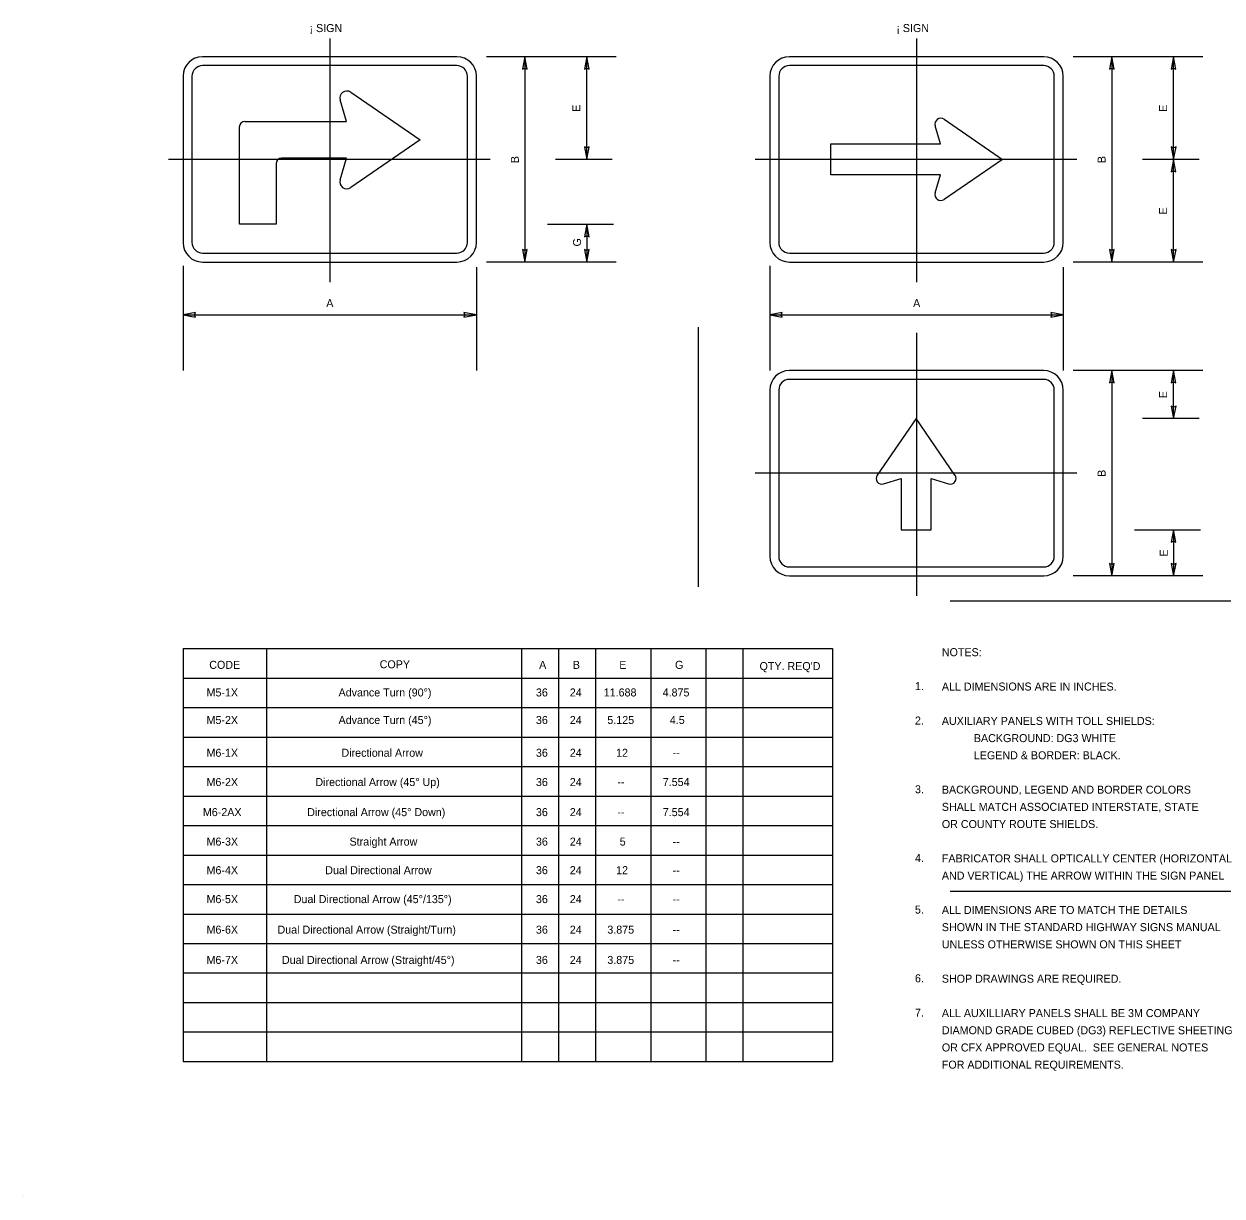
# Model space of a CAD drawing. Extents: x 60714 to 61343, y 8039 to 8449.
# Drawn here: x 60713.6 to 61132.8, y 8039 to 8449.1 of the extents above; entities that cross this region are included whole.
import ezdxf

# ---------------------------------------------------------------- set-up
doc = ezdxf.new("R2010")
doc.units = 0
for name, color, linetype in [('AdhocPoint_dp', 7, 'Continuous'), ('DimLines_dp', 7, 'Continuous'), ('SignPanel', 7, 'Continuous'), ('TextNotes', 7, 'Continuous'), ('TextTables', 7, 'Continuous')]:
    doc.layers.add(name, color=color, linetype=linetype)

msp = doc.modelspace()

# ---------------------------------------------------------------- linework, layer by layer
at = {"layer": 'AdhocPoint_dp'}
msp.add_line((60713.58, 8038.97), (60713.58, 8038.97), dxfattribs=at)
at = {"layer": 'DimLines_dp'}
for p, q in [((60820.57, 8444.01), (60820.57, 8358.79)), ((61025.91, 8444.01), (61025.91, 8358.79)), ((60920.81, 8437.66), (60875.43, 8437.66)), ((60888.88, 8437.66), (60888.04, 8433.31)), ((60888.88, 8437.66), (60888.88, 8365.8)), ((60889.69, 8433.31), (60888.88, 8437.66)), ((60910.54, 8437.66), (60909.7, 8433.31)), ((60910.54, 8401.73), (60910.54, 8437.66)), ((60911.35, 8433.31), (60910.54, 8437.66)), ((61126.14, 8437.66), (61080.77, 8437.66)), ((61094.22, 8437.66), (61093.38, 8433.31)), ((61094.22, 8437.66), (61094.22, 8365.8)), ((61095.03, 8433.31), (61094.22, 8437.66)), ((61115.88, 8437.66), (61115.04, 8433.31)), ((61115.88, 8401.73), (61115.88, 8437.66)), ((61116.69, 8433.31), (61115.88, 8437.66)), ((60888.04, 8433.31), (60888.88, 8433.64)), ((60888.88, 8433.64), (60889.69, 8433.31)), ((60909.7, 8433.31), (60910.54, 8433.64)), ((60910.54, 8433.64), (60911.35, 8433.31)), ((61093.38, 8433.31), (61094.22, 8433.64)), ((61094.22, 8433.64), (61095.03, 8433.31)), ((61115.04, 8433.31), (61115.88, 8433.64)), ((61115.88, 8433.64), (61116.69, 8433.31)), ((60910.54, 8405.75), (60909.73, 8406.08)), ((60909.73, 8406.08), (60910.54, 8401.73)), ((60910.54, 8401.73), (60911.38, 8406.08)), ((60911.38, 8406.08), (60910.54, 8405.75)), ((61115.88, 8405.75), (61115.07, 8406.08)), ((61115.07, 8406.08), (61115.88, 8401.73)), ((61115.88, 8401.73), (61116.72, 8406.08)), ((61116.72, 8406.08), (61115.88, 8405.75)), ((60876.68, 8401.73), (60764.15, 8401.73)), ((60919.44, 8401.73), (60899.62, 8401.73)), ((61082.02, 8401.73), (60969.48, 8401.73)), ((61124.77, 8401.73), (61104.95, 8401.73)), ((61115.88, 8401.73), (61115.04, 8397.38)), ((61115.88, 8365.8), (61115.88, 8401.73)), ((61116.69, 8397.38), (61115.88, 8401.73)), ((61115.04, 8397.38), (61115.88, 8397.71)), ((61115.88, 8397.71), (61116.69, 8397.38)), ((60896.81, 8379.02), (60919.89, 8379.02)), ((60910.54, 8379.02), (60909.7, 8374.67)), ((60910.54, 8379.02), (60910.54, 8365.8)), ((60911.35, 8374.67), (60910.54, 8379.02)), ((60909.7, 8374.67), (60910.54, 8375)), ((60910.54, 8375), (60911.35, 8374.67)), ((60888.88, 8369.82), (60888.07, 8370.15)), ((60888.07, 8370.15), (60888.88, 8365.8)), ((60888.88, 8365.8), (60889.72, 8370.15)), ((60889.72, 8370.15), (60888.88, 8369.82)), ((60910.54, 8369.82), (60909.73, 8370.15)), ((60909.73, 8370.15), (60910.54, 8365.8)), ((60910.54, 8365.8), (60911.38, 8370.15)), ((60911.38, 8370.15), (60910.54, 8369.82)), ((61094.22, 8369.82), (61093.41, 8370.15)), ((61093.41, 8370.15), (61094.22, 8365.8)), ((61094.22, 8365.8), (61095.06, 8370.15)), ((61095.06, 8370.15), (61094.22, 8369.82)), ((61115.88, 8369.82), (61115.07, 8370.15)), ((61115.07, 8370.15), (61115.88, 8365.8)), ((61115.88, 8365.8), (61116.72, 8370.15)), ((61116.72, 8370.15), (61115.88, 8369.82)), ((60769.24, 8364.46), (60769.24, 8327.85)), ((60871.91, 8364.01), (60871.91, 8327.85)), ((60920.81, 8365.8), (60875.43, 8365.8)), ((60974.58, 8364.46), (60974.58, 8327.85)), ((61077.24, 8364.01), (61077.24, 8327.85)), ((61126.14, 8365.8), (61080.77, 8365.8)), ((60773.59, 8348.12), (60769.24, 8347.31)), ((60769.24, 8347.31), (60871.91, 8347.31)), ((60769.24, 8347.31), (60773.59, 8346.47)), ((60773.26, 8347.31), (60773.59, 8348.12)), ((60773.59, 8346.47), (60773.26, 8347.31)), ((60871.91, 8347.31), (60867.56, 8348.15)), ((60867.56, 8348.15), (60867.89, 8347.31)), ((60867.89, 8347.31), (60867.56, 8346.5)), ((60867.56, 8346.5), (60871.91, 8347.31)), ((60978.93, 8348.12), (60974.58, 8347.31)), ((60974.58, 8347.31), (61077.24, 8347.31)), ((60974.58, 8347.31), (60978.93, 8346.47)), ((60978.6, 8347.31), (60978.93, 8348.12)), ((60978.93, 8346.47), (60978.6, 8347.31)), ((61077.24, 8347.31), (61072.89, 8348.15)), ((61072.89, 8348.15), (61073.22, 8347.31)), ((61073.22, 8347.31), (61072.89, 8346.5)), ((61072.89, 8346.5), (61077.24, 8347.31)), ((60949.64, 8252.13), (60949.64, 8343.04)), ((61025.91, 8341.08), (61025.91, 8248.98)), ((61126.14, 8327.85), (61080.77, 8327.85)), ((61094.22, 8327.85), (61093.38, 8323.5)), ((61094.22, 8327.85), (61094.22, 8255.99)), ((61095.03, 8323.5), (61094.22, 8327.85)), ((61115.88, 8327.85), (61115.04, 8323.5)), ((61115.88, 8311.05), (61115.88, 8327.85)), ((61116.69, 8323.5), (61115.88, 8327.85)), ((61093.38, 8323.5), (61094.22, 8323.83)), ((61094.22, 8323.83), (61095.03, 8323.5)), ((61115.04, 8323.5), (61115.88, 8323.83)), ((61115.88, 8323.83), (61116.69, 8323.5)), ((61115.88, 8315.07), (61115.07, 8315.4)), ((61115.07, 8315.4), (61115.88, 8311.05)), ((61115.88, 8311.05), (61116.72, 8315.4)), ((61116.72, 8315.4), (61115.88, 8315.07)), ((61124.77, 8311.05), (61104.95, 8311.05)), ((61082.02, 8291.92), (60969.48, 8291.92)), ((61102.15, 8272.13), (61125.22, 8272.13)), ((61115.88, 8272.13), (61115.04, 8267.78)), ((61115.88, 8272.13), (61115.88, 8255.99)), ((61116.69, 8267.78), (61115.88, 8272.13)), ((61115.04, 8267.78), (61115.88, 8268.11)), ((61115.88, 8268.11), (61116.69, 8267.78)), ((61094.22, 8260.01), (61093.41, 8260.34)), ((61093.41, 8260.34), (61094.22, 8255.99)), ((61094.22, 8255.99), (61095.06, 8260.34)), ((61095.06, 8260.34), (61094.22, 8260.01)), ((61115.88, 8260.01), (61115.07, 8260.34)), ((61115.07, 8260.34), (61115.88, 8255.99)), ((61115.88, 8255.99), (61116.72, 8260.34)), ((61116.72, 8260.34), (61115.88, 8260.01)), ((61126.14, 8255.99), (61080.77, 8255.99))]:
    msp.add_line(p, q, dxfattribs=at)
at = {"layer": 'SignPanel'}
for p, q in [((60826.45, 8414.96), (60824.19, 8422.51)), ((60827.92, 8425.23), (60852.2, 8408.54)), ((60790.9, 8414.96), (60826.45, 8414.96)), ((61035.54, 8415.74), (61055.94, 8401.73)), ((60788.95, 8379.02), (60788.95, 8413.01)), ((61034.31, 8407.12), (61032.41, 8413.46)), ((60852.2, 8408.54), (60827.92, 8391.86)), ((60995.88, 8407.12), (61034.31, 8407.12)), ((60995.88, 8396.34), (60995.88, 8407.12)), ((60826.45, 8402.13), (60803.74, 8402.13)), ((60824.19, 8394.58), (60826.45, 8402.13)), ((61055.94, 8401.73), (61035.54, 8387.72)), ((60801.78, 8400.17), (60801.78, 8379.02)), ((61034.31, 8396.34), (60995.88, 8396.34)), ((61032.41, 8390), (61034.31, 8396.34)), ((60801.78, 8379.02), (60788.95, 8379.02)), ((61025.75, 8311.05), (61012.13, 8291.22)), ((61039.37, 8291.22), (61025.75, 8311.05)), ((61014.34, 8288.18), (61020.51, 8290.02)), ((61020.51, 8290.02), (61020.51, 8272.13)), ((61030.99, 8272.13), (61030.99, 8290.02)), ((61030.99, 8290.02), (61037.15, 8288.18)), ((61020.51, 8272.13), (61030.99, 8272.13))]:
    msp.add_line(p, q, dxfattribs=at)
for points in [[(60865.06, 8437.66), (60776.09, 8437.66)], [(61070.4, 8437.66), (60981.42, 8437.66)], [(60769.24, 8430.82), (60769.24, 8372.64)], [(60772.38, 8430.82), (60772.38, 8372.64)], [(60865.06, 8434.53), (60776.09, 8434.53)], [(60868.77, 8372.64), (60868.77, 8430.82)], [(60871.91, 8372.64), (60871.91, 8430.82)], [(60974.58, 8430.82), (60974.58, 8372.64)], [(60977.71, 8430.82), (60977.71, 8372.64)], [(61070.4, 8434.53), (60981.42, 8434.53)], [(61074.11, 8372.64), (61074.11, 8430.82)], [(61077.24, 8372.64), (61077.24, 8430.82)], [(60776.09, 8368.93), (60865.06, 8368.93)], [(60981.42, 8368.93), (61070.4, 8368.93)], [(60776.09, 8365.8), (60865.06, 8365.8)], [(60981.42, 8365.8), (61070.4, 8365.8)], [(61070.4, 8327.85), (60981.42, 8327.85)], [(61070.4, 8324.72), (60981.42, 8324.72)], [(60974.58, 8321.01), (60974.58, 8262.83)], [(60977.71, 8321.01), (60977.71, 8262.83)], [(61074.11, 8262.83), (61074.11, 8321.01)], [(61077.24, 8262.83), (61077.24, 8321.01)], [(60981.42, 8259.12), (61070.4, 8259.12)], [(60981.42, 8255.99), (61070.4, 8255.99)]]:
    msp.add_lwpolyline(points, dxfattribs=at)
for centre, radius, start, end in [((60776.09, 8430.82), 6.84, 90, 180), ((60865.06, 8430.82), 6.84, 360, 90), ((60981.42, 8430.82), 6.84, 90, 180), ((61070.4, 8430.82), 6.84, 360, 90), ((60776.09, 8430.82), 3.71, 90, 179.9456), ((60865.06, 8430.82), 3.71, 0.0544, 90), ((60981.42, 8430.82), 3.71, 90, 179.9456), ((61070.4, 8430.82), 3.71, 0.0544, 90), ((60826.53, 8423.21), 2.44, 55.5119, 196.6443), ((60790.9, 8413.01), 1.96, 90, 180), ((61034.38, 8414.05), 2.05, 55.5119, 196.6443), ((60803.74, 8400.17), 1.96, 90, 180), ((60826.53, 8393.88), 2.44, 163.3557, 304.4881), ((61034.38, 8389.41), 2.05, 163.3557, 304.4881), ((60776.09, 8372.64), 6.84, 180, 270), ((60776.09, 8372.64), 3.71, 180, 270), ((60865.06, 8372.64), 6.84, 270, 0), ((60865.06, 8372.64), 3.71, 270, 0), ((60981.42, 8372.64), 6.84, 180, 270), ((60981.42, 8372.64), 3.71, 180, 270), ((61070.4, 8372.64), 6.84, 270, 0), ((61070.4, 8372.64), 3.71, 270, 0), ((60981.42, 8321.01), 6.84, 90, 180), ((61070.4, 8321.01), 6.84, 360, 90), ((60981.42, 8321.01), 3.71, 90, 179.9456), ((61070.4, 8321.01), 3.71, 0.0544, 90), ((61013.77, 8290.09), 2, 145.5119, 286.6443), ((61037.73, 8290.09), 2, 253.3557, 34.4881), ((60981.42, 8262.83), 6.84, 180, 270), ((60981.42, 8262.83), 3.71, 180, 270), ((61070.4, 8262.83), 6.84, 270, 0), ((61070.4, 8262.83), 3.71, 270, 0)]:
    msp.add_arc(centre, radius, start, end, dxfattribs=at)
at = {"layer": 'TextNotes'}
for p, q in [((61037.66, 8247.22), (61197.94, 8247.22)), ((61197.94, 8145.52), (61037.66, 8145.52))]:
    msp.add_line(p, q, dxfattribs=at)
at = {"layer": 'TextTables'}
for p, q in [((60769.24, 8230.55), (60996.45, 8230.55)), ((60769.24, 8230.55), (60769.24, 8086.07)), ((60798.45, 8230.55), (60798.45, 8086.07)), ((60798.45, 8230.55), (60798.45, 8158.3)), ((60887.72, 8230.55), (60887.72, 8086.07)), ((60900.64, 8230.55), (60900.64, 8086.07)), ((60913.53, 8230.55), (60913.53, 8086.07)), ((60932.89, 8230.55), (60932.89, 8086.07)), ((60952.23, 8230.55), (60952.23, 8086.07)), ((60965.14, 8230.55), (60965.14, 8086.07)), ((60996.45, 8230.55), (60996.45, 8086.07)), ((60769.24, 8220.23), (60798.45, 8220.23)), ((60798.45, 8220.23), (60887.72, 8220.23)), ((60887.72, 8220.23), (60913.53, 8220.23)), ((60913.53, 8220.23), (60932.89, 8220.23)), ((60932.89, 8220.23), (60952.23, 8220.23)), ((60952.23, 8220.23), (60996.45, 8220.23)), ((60769.24, 8209.9), (60996.45, 8209.9)), ((60769.24, 8199.58), (60996.45, 8199.58)), ((60769.24, 8189.26), (60996.45, 8189.26)), ((60769.24, 8178.94), (60996.45, 8178.94)), ((60769.24, 8168.62), (60996.45, 8168.62)), ((60769.24, 8158.3), (60996.45, 8158.3)), ((60769.24, 8147.98), (60996.45, 8147.98)), ((60769.24, 8137.66), (60996.45, 8137.66)), ((60769.24, 8127.35), (60996.45, 8127.35)), ((60769.24, 8117.03), (60996.45, 8117.03)), ((60769.24, 8106.71), (60996.45, 8106.71)), ((60769.24, 8096.39), (60996.45, 8096.39)), ((60769.24, 8086.07), (60996.45, 8086.07))]:
    msp.add_line(p, q, dxfattribs=at)

# ---------------------------------------------------------------- texts
at = {"layer": 'DimLines_dp'}
for s, p in [('¡ SIGN', (60813.51, 8446.27)), ('¡ SIGN', (61018.84, 8446.27)), ('A', (60819.37, 8350.03)), ('A', (61024.71, 8350.03))]:
    msp.add_text(s, height=2.8, dxfattribs=at).set_placement(p)
for s, p in [('E', (60908.27, 8418.39)), ('E', (61113.61, 8418.39)), ('B', (60886.75, 8400.43)), ('B', (61092.08, 8400.43)), ('E', (61113.61, 8382.46)), ('G', (60908.51, 8371.25)), ('E', (61113.61, 8318.15)), ('B', (61092.08, 8290.62)), ('E', (61113.84, 8262.75))]:
    msp.add_text(s, height=2.8, rotation=90, dxfattribs=at).set_placement(p)
at = {"layer": 'TextNotes'}
for s, p in [('NOTES:', (61034.77, 8227.88)), ('1.', (61025.36, 8215.99)), ('ALL DIMENSIONS ARE IN INCHES.', (61034.77, 8215.86)), ('2.', (61025.36, 8203.96)), ('AUXILIARY PANELS WITH TOLL SHIELDS:', (61034.77, 8203.83)), ('BACKGROUND: DG3 WHITE', (61045.97, 8197.81)), ('LEGEND & BORDER: BLACK.', (61045.97, 8191.8)), ('3.', (61025.36, 8179.91)), ('BACKGROUND, LEGEND AND BORDER COLORS', (61034.77, 8179.77)), ('SHALL MATCH ASSOCIATED INTERSTATE, STATE', (61034.77, 8173.76)), ('OR COUNTY ROUTE SHIELDS.', (61034.77, 8167.74)), ('4.', (61025.36, 8155.85)), ('FABRICATOR SHALL OPTICALLY CENTER (HORIZONTAL', (61034.77, 8155.72)), ('AND VERTICAL) THE ARROW WITHIN THE SIGN PANEL', (61034.77, 8149.7)), ('5.', (61025.36, 8137.81)), ('ALL DIMENSIONS ARE TO MATCH THE DETAILS', (61034.77, 8137.67)), ('SHOWN IN THE STANDARD HIGHWAY SIGNS MANUAL', (61034.77, 8131.66)), ('UNLESS OTHERWISE SHOWN ON THIS SHEET', (61034.77, 8125.65)), ('6.', (61025.36, 8113.75)), ('SHOP DRAWINGS ARE REQUIRED.', (61034.77, 8113.62)), ('7.', (61025.36, 8101.72)), ('ALL AUXILLIARY PANELS SHALL BE 3M COMPANY', (61034.77, 8101.59)), ('DIAMOND GRADE CUBED (DG3) REFLECTIVE SHEETING', (61034.77, 8095.58)), ('OR CFX APPROVED EQUAL.  SEE GENERAL NOTES', (61034.77, 8089.56)), ('FOR ADDITIONAL REQUIREMENTS.', (61034.77, 8083.55))]:
    msp.add_text(s, height=2.8, dxfattribs=at).set_placement(p)
at = {"layer": 'TextTables'}
for s, p in [('CODE', (60778.42, 8223.45)), ('COPY', (60838.06, 8223.64)), ('A', (60893.86, 8223.45)), ('B', (60905.67, 8223.45)), ('E', (60921.9, 8223.45)), ('G', (60941.4, 8223.45)), ("QTY. REQ'D", (60970.98, 8223.02)), ('M5-1X', (60777.47, 8213.79)), ('Advance Turn (90°)', (60823.67, 8213.79)), ('36', (60892.73, 8213.79)), ('24', (60904.59, 8213.79)), ('11.688', (60916.46, 8213.79)), ('4.875', (60937.07, 8213.79)), ('M5-2X', (60777.47, 8204.15)), ('Advance Turn (45°)', (60823.67, 8204.15)), ('36', (60892.73, 8204.15)), ('24', (60904.59, 8204.15)), ('5.125', (60917.72, 8204.15)), ('4.5', (60939.59, 8204.15)), ('M6-1X', (60777.47, 8192.68)), ('Directional Arrow', (60824.68, 8192.68)), ('36', (60892.73, 8192.68)), ('24', (60904.59, 8192.68)), ('12', (60920.78, 8192.68)), ('--', (60940.58, 8192.68)), ('M6-2X', (60777.47, 8182.44)), ('Directional Arrow (45° Up)', (60815.56, 8182.44)), ('36', (60892.73, 8182.44)), ('24', (60904.59, 8182.44)), ('--', (60921.23, 8182.44)), ('7.554', (60937.12, 8182.44)), ('M6-2AX', (60776.19, 8171.91)), ('Directional Arrow (45° Down)', (60812.7, 8171.91)), ('36', (60892.73, 8171.91)), ('24', (60904.59, 8171.91)), ('--', (60921.23, 8171.91)), ('7.554', (60937.12, 8171.91)), ('M6-3X', (60777.47, 8161.6)), ('Straight Arrow', (60827.51, 8161.6)), ('36', (60892.73, 8161.6)), ('24', (60904.59, 8161.6)), ('5', (60922.05, 8161.6)), ('--', (60940.58, 8161.6)), ('M6-4X', (60777.47, 8151.6)), ('Dual Directional Arrow', (60819.01, 8151.6)), ('36', (60892.73, 8151.6)), ('24', (60904.59, 8151.6)), ('12', (60920.78, 8151.6)), ('--', (60940.58, 8151.6)), ('M6-5X', (60777.47, 8141.47)), ('Dual Directional Arrow (45°/135°)', (60807.99, 8141.47)), ('36', (60892.73, 8141.47)), ('24', (60904.59, 8141.47)), ('--', (60921.23, 8141.47)), ('--', (60940.58, 8141.47)), ('M6-6X', (60777.47, 8130.79)), ('Dual Directional Arrow (Straight/Turn)', (60802.3, 8130.79)), ('36', (60892.73, 8130.79)), ('24', (60904.59, 8130.79)), ('3.875', (60917.72, 8130.79)), ('--', (60940.58, 8130.79)), ('M6-7X', (60777.47, 8120.19)), ('Dual Directional Arrow (Straight/45°)', (60803.86, 8120.19)), ('36', (60892.73, 8120.19)), ('24', (60904.59, 8120.19)), ('3.875', (60917.72, 8120.19)), ('--', (60940.58, 8120.19))]:
    msp.add_text(s, height=2.8, dxfattribs=at).set_placement(p)

doc.saveas('drawing.dxf')
